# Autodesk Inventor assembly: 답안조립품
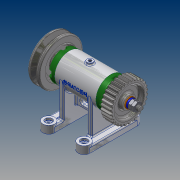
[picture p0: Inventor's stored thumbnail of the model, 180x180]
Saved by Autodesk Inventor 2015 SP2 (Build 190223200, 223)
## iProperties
Created: 2015-11
Part Number: 답안조립품
Document SubType Name: Assembly
Designer: AMC
Author: AMC
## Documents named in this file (12)
- C:\Users\AMC\Desktop\451109V1033\답안조립품.iam
- C:\Users\AMC\Desktop\451109V1033\본체.ipt
- C:\Users\AMC\Desktop\451109V1033\축.ipt
- C:\Users\AMC\Desktop\451109V1033\베어링 15 x 32 x 9.ipt
- C:\Users\AMC\Desktop\451109V1033\커버.ipt
- C:\Users\AMC\Desktop\451109V1033\V벨트풀리.ipt
- C:\Users\AMC\Desktop\451109V1033\스퍼기어.ipt
- C:\Users\AMC\Desktop\451109V1033\와셔 8x17.ipt
- C:\Users\AMC\Desktop\451109V1033\스프링와셔 8.ipt
- C:\Users\AMC\Desktop\451109V1033\너트 M 8.ipt
- C:\Users\AMC\Desktop\451109V1033\키 3 x 3 x 12.ipt
- C:\Users\AMC\Desktop\451109V1033\오일 실 15 25 7.ipt
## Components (3 placed, 2 different names)
1. KS B 2023 6002 - 15 x 32 x 9:1
2. KS B 2023 6002 - 15 x 32 x 9:2
3. V벨트풀리:1
